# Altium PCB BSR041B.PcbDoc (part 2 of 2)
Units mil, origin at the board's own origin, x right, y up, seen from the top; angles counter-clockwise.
Board outline 3820.03 x 2030.03 mil, 4 copper layers (Top Layer, MidLayer1, MidLayer2, Bottom Layer), stack 59.4 mil thick; 65 components, 15 nets, 109 pads, 61 vias.
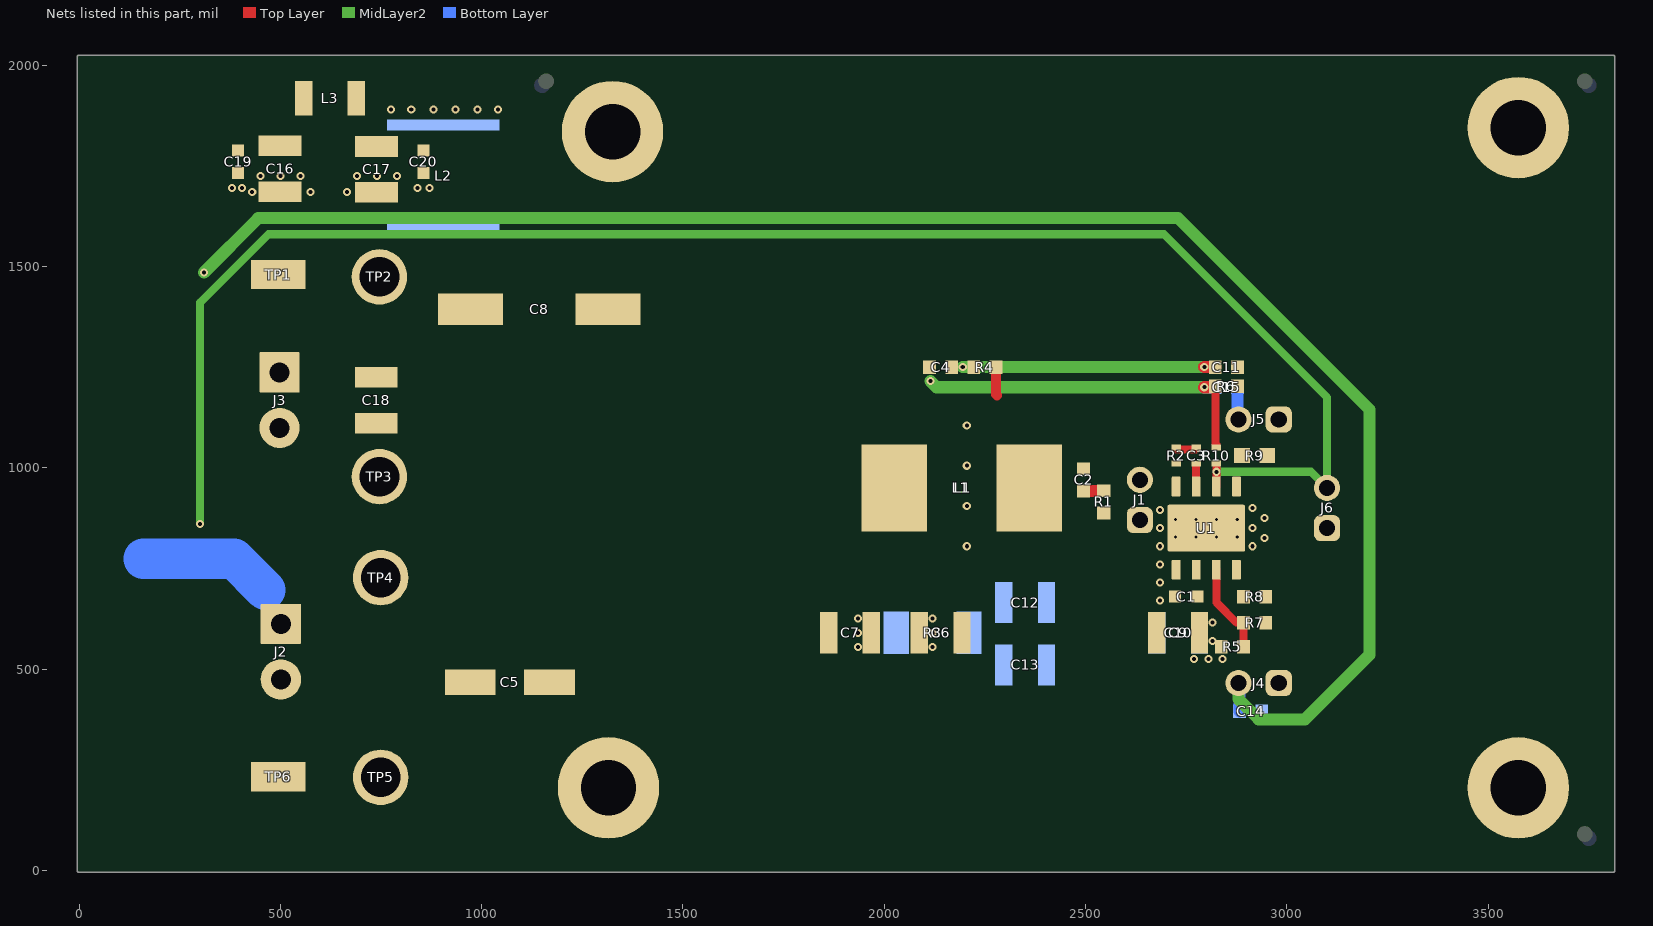
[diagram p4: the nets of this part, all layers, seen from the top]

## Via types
v1: diameter 20, hole 10, Top Layer to Bottom Layer, tented both sides, 53 vias
v2: diameter 19.68, hole 7.87, Top Layer to Bottom Layer, tented both sides, 4 vias
v3: diameter 19.68, hole 7.87, Top Layer to Bottom Layer, 4 vias

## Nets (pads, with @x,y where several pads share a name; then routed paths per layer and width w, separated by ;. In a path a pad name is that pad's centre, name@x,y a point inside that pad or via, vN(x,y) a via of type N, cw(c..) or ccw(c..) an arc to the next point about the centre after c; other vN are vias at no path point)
BST: C3.2 U1.7 | length 52.4
  Top Layer w20: U1.7@2775,950 2775,1002.44
EN: C14.1 J4.2 R5.1 R7.2 U1.3 | length 4510.5
  Top Layer w20: U1.3@2825,746.65 2825,665 2875,615 R7.2@2892.44,615 2892.56,614.88 R5.1@2892.56,555
  MidLayer2 w30: v1(310,1485) 445,1620 2730,1620 3205,1145 3205,535 3045,375 2930,375 2880,425 J4.2@2880,465
  Bottom Layer w30: J4.2@2880,465 2882.44,462.56 C14.1@2882.44,395
FB: C11.2 C15.2 J5.2 R6.1 R9.2 U1.5 | length 76
  Bottom Layer w30: C15.2@2877.56,1200 2877.56,1127.44 J5.2@2880,1125
GND: C1.1 C5.2 C6.2 C7.2 C8.2 C9.1 C10.1 C12.2 C13.2 C14.2 C16.2 C17.2 C18.2 C19.2 C20.2 J1.1 J2.1 J3.2 J4.1 J5.1 J6.1 pad.1 R1.1 R7.1 R8.1 R9.1 TP3.1 TP4.1 U1.1 U1.9@2800,850 | length 335.3
  Bottom Layer w100: 160,774 385,774 463,696
  other v1: 2685,670 2685,715 2685,760 2205,805 2685,805 2915,805 2945,825 2685,850 2915,850 2945,875 2685,895 2915,900 2205,905 2205,1005 2205,1105 430,1685 575,1685 665,1685 380,1695 405,1695 840,1695 870.26,1695 450,1725 500,1725 550,1725 690,1725 740,1725 790,1725
  other v2: 2723.23,828.35 2876.77,828.35 2723.23,871.65 2876.77,871.65
  other v3: 2774.41,828.35 2825.59,828.35 2774.41,871.65 2825.59,871.65
NetC2_2: C2.2 R1.2 | length 50
  Top Layer w30: C2.2@2495,942.44 2544.88,942.44 R1.2@2545,942.56
NetC3_1: C3.1 R2.1 | length 50
  Top Layer w20: R2.1@2725,1045 C3.1@2775,1045
NetC4_2: C4.2 C11.1 R4.2 | length 627.4
  Top Layer w30: v1(2795,1250) C11.1@2822.44,1250
  MidLayer2 w30: v1(2195,1250) v1(2795,1250)
NetC12_1: C12.1 C13.1 R3.1
NetC17_1: C17.1 C20.1 L2.1 L3.2
  other v1: 775,1890 825,1890 880,1890 935,1890 990,1890 1040,1890
PG: J6.2 R10.1 U1.6 | length 4153.8
  Top Layer w20: U1.6@2825,953.35 v1(2825,990) 2825,1002.44
  MidLayer2 w20: v1(300,860) 300,1410 470,1580 2695,1580 3100,1175 J6.2@3100,950 3060,990 v1(2825,990)
RON: R8.2 U1.4
SW: C2.1 J1.2 L1.1 R2.2 R4.1 U1.8 | length 71
  Top Layer w25: R4.1@2277.56,1250 2277.56,1182.44 2280,1180
VIN: C1.2 C8.1 C9.2 C10.2 C18.1 J3.1 L2.2 R5.2 TP1.1 TP2.1 U1.2
  other v1: 2770,525 2805,525 2840,525 2815,570 2815,615
VIN_EMI: C16.1 C19.1 L3.1
VOUT: C4.1 C5.1 C6.1 C7.1 C15.1 J2.2 L1.2 R3.2 R6.2 R10.2 TP5.1 TP6.1 | length 888.2
  Top Layer w18: R6.2@2822.44,1200 R6.2@2825,1197.44
  Top Layer w20: R6.2@2822.44,1200 2822.44,1060.12 2825,1057.56
  Top Layer w30: v1(2795,1200) R6.2@2822.44,1200
  MidLayer2 w30: v1(2115,1215) 2130,1200 v1(2795,1200)
  Bottom Layer w30: v1(2795,1200) C15.1@2822.44,1200
  other v1: 1935,555 2120,555 1935,590 2120,590 1935,625 2120,625
pads on no net: FID1.1 FID2.1 FID3.1 FID4.1 FID5.1 FID6.1 LBL1.0 SH-J4.0 U1.9@2800,850
copper on no net: | length 152.4
  Top Layer w16: v1@299,234 299,199 311,187
  Bottom Layer w20: 229,306 v1(300,235)

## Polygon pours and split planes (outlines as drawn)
GND on MidLayer1 "GND_L02_P289" (solid, remove dead copper, pour order 289): 1095,1750 605,1750 605,1445 640,1410 1095,1410
GND on MidLayer1 "GND_L02_P269" (solid, remove dead copper, pour order 269): 67.45,1453 1102,1453 1102,0 69.99,0
GND on MidLayer1 "GND_L02_P227" (solid, pour order 227): 3810,2020 3810,0 1084,0 1084,2020
NetC17_1 on Top Layer "NETC17_1_L01_P281" (solid, remove dead copper, pour order 281): 645,1970 645,1770 1060,1770 1060,1970
VOUT on Top Layer "VOUT_L01_P279" (solid, remove dead copper, pour order 279): 2095,1265 2095,1165 2130,1165 2130,1265
SW on Top Layer "SW_L01_P277" (solid, remove dead copper, pour order 277): 2260,1265 2260,1165 2295,1165 2295,1265
SW on Top Layer "SW_L01_P215" (solid, remove dead copper, pour order 215): 2260,1202 2260,707.45 2456.53,707.45 2456.53,1202
NetC4_2 on Top Layer "NETC4_2_L01_P213" (solid, remove dead copper, pour order 213): 2145,1265 2145,1215 2240,1215 2240,1235 2240,1265
FB on Top Layer "FB_L01_P217" (solid, remove dead copper, pour order 217): 2855,928.19 2910,928.19 2910,1160 2855,1160
GND on Top Layer "GND_L01_P273" (solid, remove dead copper, pour order 273): 340,1743 900,1743 900,1657 340,1657
VIN on Top Layer "VIN_L01_P238" (solid, remove dead copper, pour order 238): 48,1448 48,1191 373,1191 373,1448
VIN_EMI on Top Layer "VIN_EMI_L01_P235" (solid, remove dead copper, pour order 235): 0.01,1968 0.01,1769 587,1769 587,1968
VIN_EMI on Top Layer "VIN_EMI_L01_P275" (solid, remove dead copper, pour order 275): 0,1918 0,1658 316.5,1658 316.5,1918
GND on Top Layer "GND_L01_P265" (solid, pour order 265): 3807.11,2021.62 3807.11,1.62 1100.11,1.62 1100.11,2021.62
RON on Top Layer "RON_L01_P234" (solid, pour order 234): 2864.41,665 2910,665 2910,770 2864.41,770
VIN on Top Layer "VIN_L01_P225" (solid, remove dead copper, pour order 225): 2757.17,770.65 2852.2,770.65 2852.2,515 2757.17,515
GND on Top Layer "GND_L01_P228" (solid, remove dead copper, pour order 228): 0,1136 0,569 1223,569 1223,1136
VIN on Top Layer "VIN_L01_P229" (solid, remove dead copper, pour order 229): 334,1605 334,1192 1064,1192 1064,1605
VOUT on Top Layer "VOUT_L01_P230" (solid, remove dead copper, pour order 230): 0,511 0,102 1061,102 1061,511
VIN on Top Layer "VIN_L01_P232" (solid, remove dead copper, pour order 232): 0,1604 533,1604 533,1192 0,1192
SW on Top Layer "SW_L01_P233" (solid, pour order 233): 2430,928.65 2430,1055 2757,1055 2757,928.65
VOUT on Top Layer "VOUT_L01_P221" (solid, remove dead copper, pour order 221): 1925.01,1202 2130,1202 2130,535 1925.32,535
FB on Top Layer "FB_L01_P216" (solid, remove dead copper, pour order 216): 2855,1121.73 2908.58,1121.73 2908.58,1265 2855,1265
EN on Top Layer "EN_L01_P212" (solid, remove dead copper, pour order 212): 2910,630 2910,465 2873.45,465 2873.45,630
NetC17_1 on Bottom Layer "NETC17_1_L04_P287" (solid, remove dead copper, pour order 287): 1060,1910 1060,1760 755.39,1760 755.39,1905.39 760,1910
VIN on Bottom Layer "VIN_L04_P285" (solid, remove dead copper, pour order 285): 1054.61,1685 695,1685 695,1360 1055,1360
GND on Bottom Layer "GND_L04_P283" (solid, remove dead copper, pour order 283): 10,1915 10,1660 610,1660 610,1915
VIN on Bottom Layer "VIN_L04_P208" (solid, remove dead copper, pour order 208): 2853.53,510.84 2852.69,510 2750,510 2750,650 2825,650 2825,550 2855,550
NetC12_1 on Bottom Layer "NETC12_1_L04_P209" (solid, remove dead copper, pour order 209): 2155,650 2260,650 2260,740 2340,740 2340,435 2260,435 2260,530 2155,530
VOUT on Bottom Layer "VOUT_L04_P210" (solid, remove dead copper, pour order 210): 1919.87,651.2 2135.13,651.2 2135.13,528.8 1919.87,528.8
EN on Bottom Layer "EN_L04_P237" (solid, remove dead copper, pour order 237): 285,1604 315,1604 315,1466 285,1466
GND on Bottom Layer "GND_L04_P226" (solid, remove dead copper, pour order 226): 3810,2020 3810,6 1082,6 1074,14 1074,2023
GND on Bottom Layer "GND_L04_P231" (solid, remove dead copper, pour order 231): 334,1166 334,0 1245.45,0 1241.36,1166
PG on Bottom Layer "PG_L04_P261" (solid, remove dead copper, pour order 261): 285,980 315,980 315,845 285,845
GND on MidLayer2 "GND_L03_P271" (solid, remove dead copper, pour order 271): 1421.96,815 341,815 341,1 1423.59,1
VIN on MidLayer2 "VIN_L03_P236" (solid, remove dead copper, pour order 236): 1687.27,1565 2072.27,1180 2285,1180 2860,605 2860,494.61 2399.86,494.61 2024.73,805 345,805 345,1565
GND on MidLayer2 "GND_L03_P263" (solid, remove dead copper, pour order 263): 1078.08,2020 1085.08,2027 3813,2027 3813,3 3810,0 1084,0
VOUT on MidLayer2 "VOUT_L03_P211" (solid, remove dead copper, pour order 211): 2165,650 2165,470 2045,350 1145,350 1085,100 445,110 445,782.5 2005,782.5
VIN on Top Solder "NONET_L-01_P-001" (solid, pour order 223): 0,1609 315,1609 315,1187 0,1187

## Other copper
Top Layer:
  text ".Layer_Name" at -751,-1769.49 h60
Bottom Layer:
  text ".Layer_Name" at -751,-1769.49 h60

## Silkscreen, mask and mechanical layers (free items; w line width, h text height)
Top Overlay:
  text "EMI IN+" at 325,1885 h60
  text "VIN / 6 - 100VDCmax" at 380,1314 h70
  text "GND" at 850,950 h80
  text "GND" at 850,700 h80
  text "VOUT" at 280,690 h80
  text "12V DC/1A" at 280,290 h80
  text "DANGER HIGH VOLTAGE" at 2050,230 h40
  text "BSR041A" at 3205,130 h35
  text "VOUT_S" at 352,35 h80
  text ".Layer_Name" at -751,-1769.49 h60
Bottom Overlay:
  text "EN" at 399,1526 h40
  text "VIN" at 560,1316 h80
  text "GND" at 581,975 h80
  text "PG" at 415,902 h40
  text "GND" at 577,681 h80
  text "VOUT" at 602,332 h80
  text ".Layer_Name" at -751,-1769.49 h60
Top Paste:
  text ".Layer_Name" at -751,-1769.49 h60
Bottom Paste:
  text ".Layer_Name" at -751,-1769.49 h60
Top Solder:
  rectangle: 0,1655 316,1952
  rectangle: -1,95 315,518
  rectangle: -2,564 315,1140
  text ".Layer_Name" at -751,-1769.49 h60
  text ".Layer_Name" at -751,-1769.49 h60
Bottom Solder:
  text ".Layer_Name" at -751,-1769.49 h60
Drill Guide:
  text ".Layer_Name" at -751,-1769.49 h60
M1 Board Outline:
  lines w10: -10,0 -10,2010 0,2020 ; 315,0 0,0 ; 318,0 3810,0 ; 0,0 3810,0 ; 0,0 0,2020 ; 0,2020 3810,2020 ; 0,2020 315,2020 3810,2020 ; 3810,0 3810,2020 ; 3810,0 3810,2020
  text ".Layer_Name" at -751,-1769.49 h60
M2 Board Dimensions:
  rectangle: -1328,-1196.5 -1203,-1071.5
  rectangle: -1203,-1321.5 -828,-1196.5
  lines w7: -1328,-1196.5 -328,-1196.5 ; -1203,-1321.5 -1203,-1071.5 ; -1078,-1321.5 -1078,-1071.5 ; -828,-1321.5 -828,-1071.5 ; -578,-1321.5 -578,-1071.5 ; -1328,-1321.5 -328,-1321.5 -328,-1071.5 -1328,-1071.5 -1328,-1321.5
  text ".Layer_Name" at -751,-1769.49 h60
M3 3D STEP Top:
  text ".Layer_Name" at -751,-1769.49 h60
M4 3D STEP Bottom:
  text ".Layer_Name" at -751,-1769.49 h60
M5 Assembly Top:
  lines w10: -1620,-1841.17 4980,-1841.17 ; -1620,-1637.83 4982,-1637.83 ; -1620,-1434.5 -1620,-2044.5 2385,-2044.5 4982,-2044.5 4982,-1434.5 -1619.5,-1434.5 -1619.5,-2044.5 -44,-2044.5 ; 845,-2044.5 845,-1434.5 ; 2112,-1637.83 2112,-1434.5 ; 2952,-1637.83 2952,-1434.5 ; 3574,-2051 3574,-1848.17
  text "COMPONENTS MARKED 'DNP' SHOULD NOT BE POPULATED." at -174.5,-1229.5 h60
  text "ASSEMBLY VARIANT:" at -175,-1345 h60
  text ".VariantName" at 861,-1345 h60
  text "PCB VIEWED FROM TOP SIDE" at -1556.5,-1566.67 h60
  text "BOARD #:" at 920,-1566.67 h60
  text ".PRJ_Number" at 1465.5,-1566.67 h60
  text "REV:" at 2310,-1566.67 h60
  text ".PCB_Rev" at 2601.5,-1566.67 h60
  text "SVN REV:" at 3148,-1566.67 h60
  text ".VersionControl_RevNumber" at 3654,-1566.67 h60
  text "IGNORE ->" at -1556.5,-1769.49 h60
  text "PLOT NAME =" at -1556.5,-1975.34 h60
  text ".plot_File_Name" at -751,-1975.34 h60
  text "GENERATED    :" at 922,-1975.34 h60
  text ".Print_Date" at 1791.5,-1975.34 h60
  text ".Print_Time" at 2520.5,-1975.34 h60
  text "TEXAS INSTRUMENTS" at 3785,-1975.34 h60
M6 Assembly Bottom:
  lines w10: -1620.5,-1638.33 4981.5,-1638.33 ; -1618.5,-1841.67 4981.5,-1841.67 ; -212.5,-2051.5 -212.5,-1848.67 ; 409.5,-1638.33 409.5,-1435 ; 1249.5,-1638.33 1249.5,-1435 ; 2516.5,-2045 2516.5,-1435 ; 3405.5,-2045 4981,-2045 4981,-1435 -1620.5,-1435 -1620.5,-2045 976.5,-2045 4981.5,-2045 4981.5,-1435
  text "COMPONENTS MARKED 'DNP' SHOULD NOT BE POPULATED." at 4774,-1229 h60
  text ".VariantName" at 3730,-1345 h60
  text "ASSEMBLY VARIANT:" at 4769,-1345 h60
  text ".VersionControl_RevNumber" at -292.5,-1567.17 h60
  text "SVN REV:" at 213.5,-1567.17 h60
  text ".PCB_Rev" at 760,-1567.17 h60
  text "REV:" at 1051.5,-1567.17 h60
  text ".PRJ_Number" at 1896,-1567.17 h60
  text "BOARD #:" at 2441.5,-1567.17 h60
  text "PCB VIEWED FROM BOTTOM SIDE" at 4918,-1567.17 h60
  text "IGNORE ->" at 1219.85,-1769.49 h60
  text "TEXAS INSTRUMENTS" at -423.5,-1975.84 h60
  text ".Print_Time" at 841,-1975.84 h60
  text ".Print_Date" at 1570,-1975.84 h60
  text "GENERATED    :" at 2439.5,-1975.84 h60
  text ".plot_File_Name" at 4112.5,-1975.84 h60
  text "PLOT NAME =" at 4918,-1975.84 h60
M9 Title Sheet:
  drawing of 57 lines, arcs and shapes, not listed
  text "1" at -588.16,7125.5 h70
  text "2" at 1907.5,7125.5 h70
  text "3" at 4396.84,7125.5 h70
  text "4" at 6903.51,7125.5 h70
  text "5" at 9402.5,7125.5 h70
  text "6" at 11907.5,7125.5 h70
  text "A" at -1744.5,5982.5 h70
  text "A" at 13055.5,5982.5 h70
  text "B" at -1744.5,3602.5 h70
  text "B" at 13055.5,3602.5 h70
  text "C" at -1744.5,1227.5 h70
  text "C" at 13055.5,1227.5 h70
  text "PROJECT TITLE:" at 10015.5,-633.5 h45
  text "BSR041" at 10065.5,-766.83 h70
  text "DESIGNED FOR:" at 10015.5,-934.5 h45
  text "D" at -1744.5,-1142.5 h70
  text "D" at 13055.5,-1142.5 h70
  text "FILE NAME:" at 10015.5,-1234.5 h45
  text "Texas Instruments (TI) and/or its licensors do not warrant the accuracy or completeness of this specification" at 5046,-1516.34 h45
  text "ENGINEER:" at 10015.5,-1524.5 h45
  text "LAYOUT BY:" at 11520.5,-1524.5 h45
  text "or any information contained therein. TI and/or its licensors do not warrant that this design will meet" at 5001.01,-1629 h45
  text "Brani Dubocanin" at 10065.5,-1679.49 h70
  text "Robert Loke" at 11571,-1679.49 h70
  text "the specifications, will be suitable for your application or fit for any particular purpose, or will operate in" at 5001.01,-1741.67 h45
  text ".Layer_Name" at -751,-1769.49 h60
  text "ALTIUM DESIGNER VERSION:" at 11520.5,-1834.5 h45
  text "an implementation. TI and/or its licensors do not warrant that the design is production worthy. You should" at 5001.01,-1854.33 h45
  text "completely validate and test your design implementation to confirm the system functionality for your application." at 5046,-1967 h45
  text ".print_Scale" at 10065.5,-1967.83 h70
  text ".Application_BuildNumber" at 11571,-1967.83 h70
  text "1" at -588.16,-2174.5 h70
  text "2" at 1907.5,-2174.5 h70
  text "3" at 4396.84,-2174.5 h70
  text "4" at 6903.51,-2174.5 h70
  text "5" at 9402.5,-2174.5 h70
  text "6" at 11907.5,-2174.5 h70
M10 Fab Notes:
  drawing of 185 lines, arcs and shapes, not listed
  text "DESIGN INFORMATION" at 11053.02,4999 h60
  text "MIN. TRACK WIDTH:" at 10408.46,4819 h60
  text "8" at 11504.7,4819 h60
  text "MIL" at 11659.46,4819 h60
  text "MIN. CLEARANCE:" at 10408.46,4687 h60
  text "MIL" at 11659.46,4687 h60
  text "10" at 11478,4686 h60
  text "MIN. VIA PAD SIZE:" at 10408.46,4555 h60
  text "24" at 11474.71,4555 h60
  text "MIL" at 11659.46,4555 h60
  text "0.05mm (2MIL)" at 11103.46,4413.29 h60
  text "MINIMUM ANNULAR RING" at 10079.23,4409 h60
  text "EXTERNAL" at 11811.46,4409 h60
  text "PER" at 10279.23,4291 h60
  text "IPC-D-275 CLASS 2 LEVEL C" at 10499.23,4291 h60
  text "MIL, HOLES" at 11987.46,4178.71 h60
  text "+/-" at 11595,4178 h60
  text "+/-" at 12449,4178 h60
  text "REGISTRATION TOLERANCES:" at 10079.23,4173 h60
  text "METAL" at 11279,4173 h60
  text "5" at 11855.2,4173 h60
  text "3" at 12688.2,4173 h60
  text "MIL" at 12804.46,4173 h60
  text "MATERIAL:" at 10004.46,3963.54 h60
  text "FR-4 High Tg" at 10990.9,3823.21 h60
  text "60.2 MIL" at 12330,3820 h60
  text "FR-408" at 10425.46,3814.64 h60
  text "X" at 10837.46,3814.64 h60
  text "OTHER" at 11913.46,3814.64 h60
  text "62 MIL (1.6mm) +/-10%" at 10745.56,3651.92 h60
  text "THICKNESS:" at 10079.23,3647.64 h60
  text "OTHER" at 12030.46,3647.64 h60
  text "TOLERANCE:" at 10079.23,3489.64 h60
  text "X" at 10918.53,3489.64 h60
  text "ANSI IPC-6012 TYPE 3 CLASS 2" at 11105.48,3489.64 h60
  text "OTHER +/-" at 11105.46,3333.64 h60
  text "BOW & TWIST:" at 10079.23,3176.64 h60
  text "X" at 10918.53,3176.64 h60
  text "ANSI IPC-6012 TYPE 3 CLASS 2" at 11105.48,3176.64 h60
  text "OTHER +/-" at 11105.46,3018.13 h60
  text "DRILLING:" at 10004.46,2879.64 h60
  text "REFERENCE:" at 10079.23,2762.64 h60
  text "X" at 10727.46,2762.64 h60
  text "AS SHOWN" at 10914.46,2762.64 h60
  text "X" at 11628.46,2762.64 h60
  text "NC_DRILL FILES" at 11765.46,2762.64 h60
  text "PTH MIN COPPER THICKNESS:" at 10079.23,2604.64 h60
  text "X" at 11429.46,2604.64 h60
  text "1MIL" at 11566.46,2604.64 h60
  text "OTHER" at 12063.46,2604.64 h60
  text "BOARD FINISH:" at 10004.46,2445.64 h60
  text "SILKSCREEN:" at 10159.68,2327.64 h60
  text "X" at 11108.46,2327.64 h60
  text "TOP" at 11234.46,2327.64 h60
  text "X" at 11618.46,2327.64 h60
  text "BOTTOM" at 11745.46,2327.64 h60
  text "SILKSCREEN COLOR:" at 10159.68,2160.64 h60
  text "X" at 11107.42,2160.64 h60
  text "WHITE" at 11234.46,2160.64 h60
  text "OTHER" at 11745.46,2160.64 h60
  text "SOLDER RESIST COLOR:" at 10159.68,1990.64 h60
  text "X" at 10727.42,1831.44 h60
  text "GREEN" at 10854.46,1831.44 h60
  text "BLUE" at 11445.46,1831.44 h60
  text "OTHER" at 11983.46,1831.44 h60
  text "IMMERSION GOLD (ENIG)" at 11065.46,1642.92 h60
  text "ENEPIG" at 12403,1639.64 h60
  text "SURFACE FINISH:" at 10004.46,1638.64 h60
  text "X" at 10878.51,1638.64 h60
  text "IMM. TIN/SILVER OR EQUIV" at 10334,1481.64 h60
  text "OTHER" at 11765.46,1481.64 h60
  text "ARRAY/PANEL:" at 10004.46,1302.64 h60
  text "CUT AND TRIM PER MECH LAYER 1" at 11065.46,1298.35 h60
  text "N.C. ROUTE" at 11065.46,1146.64 h60
  text "V. SCORE" at 11931.46,1146.64 h60
  text "CERTIFICATION:" at 10004.46,1009.64 h60
  text "MATERIALS AND WORKMANSHIP FOR ALL PCBS" at 10729.46,1009.64 h60
  text "TO MEET OR EXCEED THE REQUIREMENTS OF:" at 10729.46,911.64 h60
  text "X" at 10355.96,775.13 h60
  text "ANSI IPC-A-600F CLASS ->" at 10494.96,775.13 h60
  text "X" at 12134.02,775.13 h60
  text "2" at 12252.96,775.14 h60
  text "1" at 11937.96,773.64 h60
  text "3" at 12606.96,773.64 h60
  text "X" at 10358.02,615.64 h60
  text "UL 94V-0" at 10494.96,615.64 h60
  text "X" at 11170.02,615.64 h60
  text "RoHS" at 11306.96,615.64 h60
  text "OTHER" at 11951.36,615.64 h60
  text "PER ORDER" at 12348.42,615.64 h60
  text "ADDITIONAL REQUIREMENTS:" at 10004.46,474.64 h60
  text "MICROSECTION:" at 10079.23,359.64 h60
  text "YES" at 10984.96,359.64 h60
  text "X" at 11267,205 h60
  text "REQUIRED" at 11846.46,203.49 h60
  text "BARE BOARD ELEC. TEST:" at 10079.23,200.64 h60
  text "NONE" at 11384.96,200.64 h60
  text "PER ORDER" at 12438.46,200.64 h60
  text "MANUFACTURER'S UL:" at 10079.23,43.64 h60
  text "RAIL" at 11244.96,39.35 h60
  text "METAL" at 11736.77,39.35 h60
  text "X" at 12112,39 h60
  text "SILK" at 12248.46,39.35 h60
  text ".Layer_Name" at -751,-1769.49 h60
M11 Gerber Information:
  lines w10: -1620,-1841.17 4980,-1841.17 ; -1620,-1637.83 4982,-1637.83 ; -1620,-1434.5 -1620,-2044.5 2385,-2044.5 4982,-2044.5 4982,-1434.5 -1619.5,-1434.5 -1619.5,-2044.5 -44,-2044.5 ; 845,-2044.5 845,-1434.5 ; 2112,-1637.83 2112,-1434.5 ; 2952,-1637.83 2952,-1434.5 ; 3574,-2051 3574,-1848.17
  text "ALL ARTWORK VIEWED FROM TOP SIDE" at -1556.5,-1566.67 h60
  text "BOARD #:" at 920,-1566.67 h60
  text ".PRJ_Number" at 1465.5,-1566.67 h60
  text "REV:" at 2310,-1566.67 h60
  text ".PCB_Rev" at 2601.5,-1566.67 h60
  text "SVN REV:" at 3148,-1566.67 h60
  text ".VersionControl_RevNumber" at 3654,-1566.67 h60
  text "LAYER NAME =" at -1556.5,-1769.49 h60
  text "PLOT NAME =" at -1556.5,-1975.34 h60
  text ".plot_File_Name" at -751,-1975.34 h60
  text "GENERATED    :" at 922,-1975.34 h60
  text ".Print_Date" at 1791.5,-1975.34 h60
  text ".Print_Time" at 2520.5,-1975.34 h60
  text "TEXAS INSTRUMENTS" at 3785,-1975.34 h60
M12 Stackup:
  drawing of 295 lines, arcs and shapes, not listed
  text "Layer" at 4920.34,6560 h60
  text "Name" at 5330.26,6560 h60
  text "Material" at 6260,6560 h60
  text "Thickness" at 7119.77,6560 h60
  text "Constant" at 7769.6,6560 h60
  text "Board Layer Stack" at 8339.46,6560 h60
  text "1" at 4920.34,6440 h60
  text "Top Overlay" at 5330.26,6440 h60
  text "2" at 4920.34,6320 h60
  text "Top Solder" at 5330.26,6320 h60
  text "Solder Resist" at 6260,6320 h60
  text "0.40mil" at 7119.77,6320 h60
  text "3.5" at 7769.6,6320 h60
  text "3" at 4920.34,6200 h60
  text "Top Layer" at 5330.26,6200 h60
  text "Copper" at 6260,6200 h60
  text "2.80mil" at 7119.77,6200 h60
  text "4" at 4920.34,6080 h60
  text "Dielectric1" at 5330.26,6080 h60
  text "FR-4" at 6260,6080 h60
  text "10.00mil" at 7119.77,6080 h60
  text "4.8" at 7769.6,6080 h60
  text "5" at 4920.34,5960 h60
  text "MidLayer1" at 5330.26,5960 h60
  text "Copper" at 6260,5960 h60
  text "1.40mil" at 7119.77,5960 h60
  text "6" at 4920.34,5840 h60
  text "Dielectric2" at 5330.26,5840 h60
  text "FR-4" at 6260,5840 h60
  text "31.00mil" at 7119.77,5840 h60
  text "4.8" at 7769.6,5840 h60
  text "7" at 4920.34,5720 h60
  text "MidLayer2" at 5330.26,5720 h60
  text "Copper" at 6260,5720 h60
  text "1.40mil" at 7119.77,5720 h60
  text "8" at 4920.34,5600 h60
  text "Dielectric3" at 5330.26,5600 h60
  text "FR-4" at 6260,5600 h60
  text "10.00mil" at 7119.77,5600 h60
  text "4.8" at 7769.6,5600 h60
  text "9" at 4920.34,5480 h60
  text "Bottom Layer" at 5330.26,5480 h60
  text "Copper" at 6260,5480 h60
  text "2.80mil" at 7119.77,5480 h60
  text "10" at 4920.34,5360 h60
  text "Bottom Solder" at 5330.26,5360 h60
  text "Solder Resist" at 6260,5360 h60
  text "0.40mil" at 7119.77,5360 h60
  text "3.5" at 7769.6,5360 h60
  text "11" at 4920.34,5240 h60
  text "Bottom Overlay" at 5330.26,5240 h60
  text ".Layer_Name" at -751,-1769.49 h60
M13 Component Bodies Top:
  text ".Layer_Name" at -751,-1769.49 h60
M14 Component Bodies Bottom:
  text ".Layer_Name" at -751,-1769.49 h60
M15 Courtyards Top:
  circle w7: c1325,1835 r135.83
  circle w7: c1315,205 r135.83
  circle w7: c3595,1845 r135.83
  circle w7: c3595,205 r135.83
  text ".Layer_Name" at -751,-1769.49 h60
M16 Courtyards Bottom:
  text ".Layer_Name" at -751,-1769.49 h60
Drill Drawing:
  circle w10: c2680.05,3613.33 r33.33
  lines w10: 2646.71,3730 2680.05,3746.67 2713.38,3730 2696.71,3763.33 2713.38,3796.67 2680.05,3780 2646.71,3796.67 2663.38,3763.33 2646.71,3730 ; 2646.71,3880 2713.38,3880 2713.38,3946.67 2646.71,3946.67 2646.71,3880 ; 2646.71,4046.67 2663.38,4046.67 2663.38,4030 2696.71,4030 2696.71,4046.67 2713.38,4046.67 2713.38,4080 2696.71,4080 2696.71,4096.67 2663.38,4096.67 2663.38,4080 2646.71,4080 2646.71,4046.67 ; 2646.71,4196.67 2663.38,4196.67 2680.05,4180 2696.71,4196.67 2713.38,4196.67 2696.71,4213.33 2713.38,4230 2696.71,4230 2680.05,4246.67 2663.38,4230 2646.71,4230 2663.38,4213.33 2646.71,4196.67 ; 2646.71,4330 2713.38,4330 2713.38,4396.67 2646.71,4396.67 2646.71,4330 ; 2660.05,3893.33 2700.05,3893.33 2700.05,3933.33 2660.05,3933.33 2660.05,3893.33
  lines w15: 2586.92,3535 9677,3535 ; 2586.92,4435 9677,4435 ; 3137.8,3385 3137.8,4585 ; 3667.66,3385 3667.66,4585 ; 4817.33,3385 4817.33,4585 ; 5323.2,3385 5323.2,4585 ; 6057,3385 6057,4585 ; 7556.55,3385 7556.55,4585 ; 8146.4,3385 8146.4,4585 ; 8892.2,3385 8892.2,4585 ; 2586.92,3385 9677,3385 9677,4585 2586.92,4585 2586.92,3385
  text "Drill Table" at 2591,4567 h60
  text "Symbol" at 2676.92,4480 h72
  text "Count" at 3182.8,4480 h72
  text "Hole Size" at 3712.66,4480 h72
  text "Plated" at 4862.33,4480 h72
  text "Hole Type" at 5368.2,4480 h72
  text "Drill Layer Pair" at 6102,4480 h72
  text "Via/Pad" at 7601.55,4480 h72
  text "Pad Shape" at 8191.4,4480 h72
  text "Template" at 8937.2,4480 h72
  text "4" at 3182.8,4330 h60
  text "50.00mil (1.270mm)" at 3712.66,4330 h60
  text "PTH" at 4862.33,4330 h60
  text "Round" at 5368.2,4330 h60
  text "Top Layer - Bottom Layer" at 6102,4330 h60
  text "Pad" at 7601.55,4330 h60
  text "(Mixed)" at 8191.4,4330 h60
  text "(Mixed)" at 8937.2,4330 h60
  text "4" at 3182.8,4180 h60
  text "98.43mil (2.500mm)" at 3712.66,4180 h60
  text "PTH" at 4862.33,4180 h60
  text "Round" at 5368.2,4180 h60
  text "Top Layer - Bottom Layer" at 6102,4180 h60
  text "Pad" at 7601.55,4180 h60
  text "Rounded" at 8191.4,4180 h60
  text "c350h250" at 8937.2,4180 h60
  text "4" at 3182.8,4030 h60
  text "137.80mil (3.500mm)" at 3712.66,4030 h60
  text "PTH" at 4862.33,4030 h60
  text "Round" at 5368.2,4030 h60
  text "Top Layer - Bottom Layer" at 6102,4030 h60
  text "Pad" at 7601.55,4030 h60
  text "Rounded" at 8191.4,4030 h60
  text "c640h350" at 8937.2,4030 h60
  text "8" at 3182.8,3880 h60
  text "7.87mil (0.200mm)" at 3712.66,3880 h60
  text "PTH" at 4862.33,3880 h60
  text "Round" at 5368.2,3880 h60
  text "Top Layer - Bottom Layer" at 6102,3880 h60
  text "Via" at 7601.55,3880 h60
  text "Rounded" at 8191.4,3880 h60
  text "(Mixed)" at 8937.2,3880 h60
  text "8" at 3182.8,3730 h60
  text "40.00mil (1.016mm)" at 3712.66,3730 h60
  text "PTH" at 4862.33,3730 h60
  text "Round" at 5368.2,3730 h60
  text "Top Layer - Bottom Layer" at 6102,3730 h60
  text "Pad" at 7601.55,3730 h60
  text "(Mixed)" at 8191.4,3730 h60
  text "(Mixed)" at 8937.2,3730 h60
  text "53" at 3182.8,3580 h60
  text "10.00mil (0.254mm)" at 3712.66,3580 h60
  text "PTH" at 4862.33,3580 h60
  text "Round" at 5368.2,3580 h60
  text "Top Layer - Bottom Layer" at 6102,3580 h60
  text "Via" at 7601.55,3580 h60
  text "Rounded" at 8191.4,3580 h60
  text "v51h25m0mx0" at 8937.2,3580 h60
  text "81 Total" at 3182.8,3430 h60
  text ".Layer_Name" at -751,-1769.49 h60

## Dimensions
3810,2020 to 3810,0 on M2 Board Dimensions
0,0 to 3810,0 on M2 Board Dimensions
-1328,-1321.5 to -328,-1321.5 on M2 Board Dimensions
